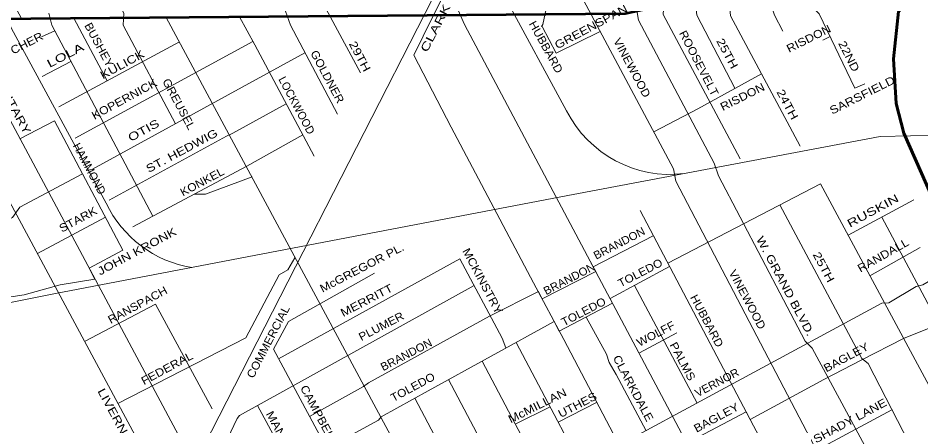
# Model space of a CAD drawing. Extents: x 34705 to 138605, y 34275 to 143551.
# Drawn here: x 81081 to 89542, y 96052 to 99871 of the extents above; entities that cross this region are included whole.
import ezdxf
from ezdxf.enums import TextEntityAlignment as Align

# ---------------------------------------------------------------- set-up
doc = ezdxf.new("R2010")
doc.units = 0
doc.header["$LTSCALE"] = 30
for name, color, linetype, lineweight in [('1', 7, 'Continuous', 13), ('11', 7, 'Continuous', 13), ('50', 7, 'Continuous', 13), ('51', 7, 'Continuous', 35)]:
    doc.layers.add(name, color=color, linetype=linetype, lineweight=lineweight)

msp = doc.modelspace()

# ---------------------------------------------------------------- linework, layer by layer
at = {"layer": '1'}
for p, q in [((80674.92, 100677.06), (81112.95, 99866.12)), ((81604.13, 99870.4), (81915.65, 99283.42)), ((81301.12, 99696.71), (81424.19, 99752.12)), ((88623.62, 99664.15), (88691.63, 99698.16)), ((81615.36, 98747.86), (83281.38, 99653.22)), ((81778.3, 98456.8), (83769.19, 99546.78)), ((81306.94, 99324.16), (81574.62, 99463.86)), ((81096.45, 98741.43), (81422.86, 98907.65)), ((81422.86, 98907.65), (82063.69, 97698.28)), ((88600.2, 98320.64), (90094.32, 95540.39)), ((88859.11, 97838.87), (89474.93, 98168.04)), ((81261.79, 97665.87), (81900.67, 98005.93)), ((89174.85, 98007.64), (89907.59, 96630.12)), ((89063.97, 97457.65), (89534.64, 97724.26)), ((83521.31, 96681.11), (85219.59, 97617.8)), ((86856.53, 97366.74), (87443.67, 96264.66)), ((81704.27, 96843.42), (82369.07, 97193.74)), ((82369.07, 97193.74), (82898.67, 96211.72)), ((86905.1, 96736.64), (87254.26, 96922.92)), ((83323.52, 96242.99), (83640.82, 95661.07)), ((85740.94, 96068.52), (86066.48, 96231.34)), ((86143.05, 96086.12), (86500.66, 96270.95)), ((88563.58, 95826.29), (89271.09, 96204.61))]:
    msp.add_line(p, q, dxfattribs=at)
for points in [[(82721.62, 108639.05), (82793.72, 106029.87), (82865.87, 105951.13), (86037.49, 99963.46), (86030.93, 99956.9), (85998.14, 99812.54), (85985.02, 99792.85), (85991.58, 99792.85), (86122.77, 99543.5), (86536.3, 99746.94)], [(75461.99, 108389.33), (75949.8, 107475.21), (75982.05, 107419.91), (76018.91, 107313.91), (77396.45, 104728.46), (77433.31, 104686.98), (77737.38, 104216.9), (82924.91, 94574.55), (82977.39, 94535.18), (83082.34, 94397.38), (83174.18, 94325.2), (83252.9, 94239.89), (83370.97, 94092.26), (86141.27, 88934.48)], [(84387.04, 107890.41), (84335.25, 107768.76), (84177.82, 107414.42), (84210.62, 107394.74), (84276.21, 107263.5), (84682.92, 106397.34), (84794.43, 106154.55), (85292.97, 105098.09), (87356, 100718.07), (87415.04, 100639.33), (87749.58, 99989.71), (87756.14, 99891.28), (88410.83, 98673.02)], [(85578.43, 106448.85), (86791.86, 103651.21), (86857.46, 103506.85), (87913.58, 101059.29), (87972.61, 100967.42), (88005.41, 100914.93), (88464.59, 100029.08), (88589.23, 99910.97), (88923.77, 99215.41), (89015.61, 99254.78)], [(85117.65, 106296.22), (85168.34, 106187.36), (87683.99, 100855.87), (87736.46, 100796.82), (88123.49, 100035.64), (88169.41, 99897.84), (88248.05, 99750)], [(84536.17, 106059.93), (85076.5, 104912.73), (87113.29, 100606.52), (87146.09, 100560.59), (87428.16, 100009.39), (87441.28, 99897.84), (87799.38, 99213.97)], [(84288.71, 105946.27), (86850.9, 100527.78), (86896.82, 100455.6), (87132.97, 99996.27), (87126.41, 99904.4), (87847.98, 98552.66)], [(83944.94, 105858.26), (84407.41, 104899.6), (85247.05, 103134.47), (85273.29, 103095.09), (85312.65, 103009.79), (86306.44, 101019.92), (86450.76, 100875.56), (86857.46, 100075.01), (86896.82, 99851.91), (87605.27, 98513.29), (87644.63, 98395.18), (88458.03, 96846.58), (88523.63, 96780.96), (89683.06, 94633.6), (89886.41, 94266.14), (90011.05, 94036.48), (90103.12, 93970.1), (90563.88, 93097.88)], [(83551.57, 105605.49), (84853.47, 102911.36), (84892.83, 102826.06), (87224.8, 98460.8), (87244.48, 98342.68), (88545.24, 95860.37), (89368.06, 94331.32)], [(82202.94, 105549.99), (85204.41, 99943.77), (85263.45, 99812.54), (88077.23, 94520.03), (88429.84, 93859.47), (88435.83, 93848.46)], [(80478.99, 102908.46), (81488.33, 101001.86), (82072.15, 99915.88), (82065.59, 99804.33), (82555.16, 98882.12)], [(79319.72, 102029.25), (80445.33, 99929.01), (80753.64, 99354.85), (80806.12, 99282.67), (82682.2, 95785.2)], [(82897.91, 101956.49), (83403.77, 101005.15), (84289.33, 99358.13)], [(83154.61, 100876.53), (83594, 100060.24), (83587.44, 99935.57), (83633.36, 99804.33), (84072.86, 98970.98), (84072.86, 98970.98)], [(85097.11, 100144.17), (84876.42, 99702.63), (84791.15, 99525.46), (85138.81, 98849.59), (85912.86, 97392.86), (86194.93, 96861.35), (87093.61, 95155.26), (89140.06, 91303.04)], [(81370.26, 99915.88), (81396.49, 99804.33), (82345.13, 98016.18)], [(82469.51, 99877.93), (86021.78, 93268.36), (87823.93, 89860.92)], [(83154.48, 99883.89), (83298.82, 99620.6), (83856.39, 98577.26)], [(81464.06, 99038.92), (81464.06, 99038.92), (82592.17, 99649.69)], [(87039.54, 98807.59), (87452.12, 99022.91), (88046.94, 99350.17)], [(81935.42, 98165.74), (83035.27, 98765.32), (83093.46, 98794.43), (83594.73, 99066.88)], [(82156.55, 97915.43), (83224.4, 98485.91), (83748.13, 98776.96)], [(79570.25, 97209.17), (81027.61, 98002.75), (81097.44, 98101.71), (81685.03, 98412.88)], [(82732.66, 98223.95), (82837.41, 98223.95), (83273.74, 98383.79)], [(82633.73, 95113.99), (84458.09, 96105.04), (84484.28, 96137.06), (84923.63, 96381.55), (86104.85, 97031.09), (86153.29, 96939.81), (86652.17, 97200.46), (86628.86, 97244.3), (87186.7, 97544.09), (87169.86, 97575.99), (88600.2, 98320.64)], [(88220.48, 98123), (88989.37, 96684.18), (89048.41, 96638.24), (89540.39, 95680.21), (89917.39, 94981.27)], [(86909.94, 98068.73), (87972.61, 96054.24), (89006.99, 94114.8)], [(83812, 96142.19), (84318.42, 96422.3), (84364.98, 96457.22), (85499.74, 97080.09), (85956.9, 97309.87), (85992.36, 97243.05), (86494.06, 97497.85), (86471.36, 97540.55), (87033.13, 97831.02)], [(90259.92, 97790.34), (90118.26, 97696.67), (89560.52, 97372.09), (89497, 97356.72), (89242.4, 97205.72), (89176.52, 97200.37)], [(72840.79, 95705.51), (75339.24, 96190.9), (75740.78, 96260.76), (75996.82, 96348.08), (76287.79, 96458.68), (77021.02, 96831.23), (77480.75, 96842.88), (77899.73, 96936.01), (78301.27, 96941.84), (79337.1, 96982.58), (79686.26, 97023.33), (80218.73, 97133.93), (80864.67, 97238.72), (81138.18, 97279.46), (81475.69, 97374.06), (81801.14, 97427.72), (81747.3, 97528.08), (82063.69, 97698.28)], [(82016.42, 96263.21), (83215.66, 96877.8), (83527, 97467.2), (83608.47, 97513.77), (83673.27, 97627.21)], [(85219.59, 97617.8), (85617.67, 96874.47), (85650.47, 96782.6)], [(84420.53, 97481.45), (83613.68, 97028.68), (83473.49, 96769.77)], [(85353.77, 97367.24), (83154.5, 96149.39), (83134.82, 96123.15), (83042.99, 95932.85), (83298.82, 95480.08)], [(89176.52, 97200.37), (85118.47, 95012.38), (83748.97, 94259.17), (83663.06, 94238.95), (82687.74, 94173.23), (82081.32, 94173.23), (81867.81, 94178.29), (81135.06, 94319.83), (79875.47, 94474.01), (79467.4, 94582.7), (79159.14, 94668.63), (78557.77, 94683.8), (78406.17, 94688.86), (78108.01, 94759.63), (77819.96, 94840.51), (76700.62, 94653.47), (76422.68, 94577.64), (75972.91, 94340.05), (75418.3, 93641.17), (74705.75, 92822.24)], [(86403.84, 97070.71), (86595.07, 96723.55), (86621.31, 96644.81), (86686.91, 96533.25), (86966.3, 96007.57)], [(87348.77, 95890.22), (87903.33, 96185.57), (87941.55, 96113.13), (88633.43, 96486.33), (88988.41, 96672.61), (89378.3, 96870.53), (89874.49, 97069.92)], [(85748.21, 96834.98), (86581.95, 95253.69), (87567.35, 93393.37)], [(83473.49, 96769.77), (83974.47, 95840.99), (83981.03, 95795.05), (84715.72, 94410.5), (84755.07, 94364.57), (85483.2, 93012.83), (85483.2, 92966.89), (85768.25, 92431.92)], [(85429.29, 96659.61), (86260.53, 95083.08), (87254.45, 93221.31)], [(85115.74, 96487.19), (85939.1, 94925.6), (86935.36, 93052.03)], [(84799.57, 96312.51), (85624.23, 94748.43), (86618.76, 92884.74)]]:
    msp.add_lwpolyline(points, dxfattribs=at)
at = {"layer": '1', "lineweight": 53}
msp.add_lwpolyline([(70273.25, 98655.39), (71057.35, 98936.8), (71901.7, 99280.47), (72734.73, 99461.12), (73549.47, 99618.3), (74194.43, 99751.98), (74462.66, 99868.63), (74760.14, 99892.09), (75412.24, 99851.32), (76511.78, 99857.14), (78835.21, 99868.78), (80080.52, 99857.14), (86770.24, 99915.34), (86956.45, 99956.09), (88909.68, 99973.56), (89759.8, 99996.86), (90394.28, 99932.82), (90847.72, 99926.99), (94474.35, 99938.64), (95736.38, 99991), (96334.87, 100081.57)], dxfattribs=at)
at = {"layer": '50'}
for p, q in [((76011.2, 82573.38), (90524.22, 110902)), ((86222.09, 99001.86), (85563.59, 100213.69))]:
    msp.add_line(p, q, dxfattribs=at)
for points in [[(81906.05, 98139.06), (81018.13, 99774.79), (76672.7, 108508.16)], [(72952.8, 95508.64), (78064.89, 96622.26), (81430.09, 97291.04), (86167.76, 98196.23), (89160.46, 98763.08), (89727.54, 98776.38), (90401.7, 98740.87), (90973.35, 98653.39), (91592.71, 98503.02), (92169.12, 98306.86)]]:
    msp.add_lwpolyline(points, dxfattribs=at)
for centre, radius, start, end in [((87193.02, 99497.41), 1090.08, 207.03912, 276.89917), ((82882.27, 98601.9), 1080.38, 205.36629, 260.7893)]:
    msp.add_arc(centre, radius, start, end, dxfattribs=at)
at = {"layer": '51', "lineweight": 60}
msp.add_lwpolyline([(100708.3, 104431.99), (100301.7, 104046.37), (99460.75, 103701.33), (98388.89, 103068.27), (97510.88, 102543.58), (96878.03, 102018.88), (96266.56, 101672.41), (94157.06, 101062.17), (92788.73, 100605.91), (92053.25, 100332.16), (91322.06, 100332.16), (90426.94, 100400.6), (89697.17, 100337.86), (89332.28, 99932.93), (89286.67, 99488.08), (89309.48, 99071.74), (89383.59, 98792.29), (89913.82, 97593.19), (90193.19, 96937.32), (90347.13, 96349.89), (90369.93, 95910.74)], dxfattribs=at)

# ---------------------------------------------------------------- texts
at = {"layer": '11'}
for s, rotation, width, p in [('CLARK  ', 62.839, 1.45, (85043.04, 99795.7)), ('GREENSPAN ', 28.155, 1.2, (86482.7, 99764.13)), ('BUSHEY', 298.223, 1.1, (81806.94, 99603.17)), ('HUBBARD', 298.873, 1.1, (85995.3, 99582.27)), ('RISDON', 26.571, 1.15, (88506.85, 99645.52)), ('FLETCHER', 27.195, 1.15, (81053.92, 99538.72)), ('VINEWOOD', 298.153, 1.1, (86801.33, 99388.73)), ('ROOSEVELT', 297.457, 1.1, (87428.64, 99431.13)), ('25TH', 298.158, 1.25, (87694.04, 99521.99)), ('LOLA ', 27.195, 1.45, (81558.55, 99498.7)), ('29TH', 298.132, 1.25, (84250.81, 99494.84)), ('22ND', 296.84, 1.2, (88834.28, 99497.09)), ('KULICK', 28.432, 1.25, (82074.7, 99403.65)), ('GOLDNER', 298.193, 1.1, (83946.56, 99304.26)), ('MILITARY', 298.614, 1.3, (80995.53, 99039.75)), ('KOPERNICK', 28.521, 1.15, (82094.44, 99079.36)), ('GREUSEL', 298.193, 1.1, (82555.14, 99047.94)), ('RISDON', 26.571, 1.15, (87886.11, 99100.55)), ('SARSFIELD', 26.571, 1.2, (89008.7, 99115.88)), ('24TH', 298.157, 1.25, (88258.83, 99044.66)), ('OTIS', 28.7, 1.35, (82275.06, 98786.9)), ('ST. HEDWIG', 28.192, 1.25, (82632.94, 98595.94)), ('KONKEL', 28.113, 1.1, (82822.65, 98305.3)), ('RUSKIN ', 28.455, 1.4, (89126.83, 98043.19)), ('STARK', 28.195, 1.15, (81660.33, 97952.44)), ('JOHN KRONK ', 28.191, 1.25, (82226.45, 97662.14)), ('BRANDON', 27.456, 1.05, (86731.94, 97729.77)), ('W. GRAND BLVD.', 297.901, 1.25, (88238.4, 97344.31)), ('RANDALL', 29.529, 1.15, (89206.26, 97618.14)), ('McGREGOR PL.', 27.499, 1.15, (84320.11, 97500.67)), ('MCKINSTRY', 297.899, 1.15, (85400.73, 97391.92)), ('25TH', 298.158, 1.25, (88598.16, 97522.1)), ('BRANDON', 27.456, 1.05, (86262.9, 97397.23)), ('TOLEDO', 27.457, 1.1, (86928.36, 97452.75)), ('VINEWOOD', 297.899, 1.1, (87882.24, 97219.13)), ('RANSPACH', 28.295, 1.1, (82218.23, 97152.21)), ('MERRITT', 27.5, 1.2, (84364.52, 97194.92)), ('TOLEDO', 27.457, 1.1, (86397.25, 97089.04)), ('HUBBARD', 297.9, 1.1, (87503.02, 97018.93)), ('COMMERCIAL', 62.514, 1.1, (83457.72, 96823.21)), ('PLUMER', 27.498, 1.1, (84501.28, 96952.05)), ('WOLFF', 27.457, 1.1, (87074.76, 96881.83)), ('BRANDON', 27.5, 1.05, (84736.11, 96686.05)), ('PALMS', 297.9, 1.15, (87276.11, 96639.78)), ('BAGLEY', 28.224, 1.15, (88859.42, 96662.2)), ('FEDERAL', 28.296, 1.15, (82494.1, 96559.53)), ('CLARKDALE', 297.9, 1.15, (86813.13, 96387.54)), ('VERNOR', 27.902, 1.05, (87647.73, 96425.45)), ('TOLEDO', 28.222, 1.1, (84797.4, 96382.92)), ('LIVERNOIS', 298.297, 1.3, (81987.52, 96073.13)), ('CAMPBELL', 298.295, 1.15, (83867.64, 96138.14)), ('McMILLAN', 26.573, 1.2, (85963.68, 96208.42)), ('UTHES', 27.332, 1.15, (86339.93, 96216.02)), ('SHADY LANE', 28.132, 1.2, (88894.7, 96067.91)), ('BAGLEY', 28.224, 1.15, (87642.58, 96097.38)), ('MANSON ', 298.297, 1.2, (83534.24, 95919.27)), ('PORTER', 27.904, 1.1, (89721.43, 95920.85))]:
    msp.add_text(s, height=75, rotation=rotation, dxfattribs=dict(at, width=width)).set_placement(p, align=Align.CENTER)
for s, rotation, p in [('LOCKWOOD', 298.193, (83658.76, 99036.56)), ('HAMMOND', 298.223, (81716.51, 98443.31))]:
    msp.add_text(s, height=75, rotation=rotation, dxfattribs=at).set_placement(p, align=Align.CENTER)

doc.saveas('drawing.dxf')
